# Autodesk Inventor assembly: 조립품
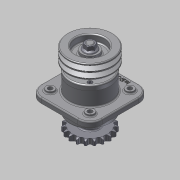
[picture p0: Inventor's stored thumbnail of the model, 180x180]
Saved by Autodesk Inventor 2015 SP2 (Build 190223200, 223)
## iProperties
Created: 2015-07
Part Number: 조립품
Document SubType Name: Assembly
Designer: AMC
Author: AMC
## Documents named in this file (12)
- C:\Users\AMC\Desktop\450735V1007\조립품.iam
- C:\Users\AMC\Desktop\450735V1007\본체.ipt
- C:\Users\AMC\Desktop\450735V1007\2-커버.ipt
- C:\Users\AMC\Desktop\450735V1007\3-축.ipt
- C:\Users\AMC\Desktop\450735V1007\4-V벨트풀리.ipt
- C:\Users\AMC\Desktop\450735V1007\5-체인 스프로킷.ipt
- C:\Users\AMC\Desktop\450735V1007\6-베어링 6206.ipt
- C:\Users\AMC\Desktop\450735V1007\7-부시.ipt
- C:\Users\AMC\Desktop\450735V1007\8-오일실 30x42.ipt
- C:\Users\AMC\Desktop\450735V1007\9-M16-너트.ipt
- C:\Users\AMC\Desktop\450735V1007\10-M6.ipt
- C:\Users\AMC\Desktop\450735V1007\11-키 6x6.ipt
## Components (22 placed, 10 different names)
1. 2-커버:1
2. 3-축:1
3. 4-V벨트풀리:1 — 각도:1
4. 5-체인 스프로킷:1 — 각도:2
5. 6-베어링 6206:1
6. 7-부시:1
7. 8-8-오일실 30x42:1
8. 9-M16 너트:1
9. 10-M6:1
10. 11-키 6x6:1 — 각도:2
11. 2-커버:2
12. 6-베어링 6206:2
13. 8-8-오일실 30x42:2
14. 10-M6:2
15. 10-M6:3
16. 10-M6:4
17. 10-M6:5
18. 10-M6:6
19. 10-M6:7
20. 10-M6:8
21. 11-키 6x6:2 — 각도:1
22. 9-M16 너트:2
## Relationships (2: Angle 2)
- 각도:1 [Angle]: 4-V벨트풀리:1 ↔ 11-키 6x6:2
- 각도:2 [Angle]: 5-체인 스프로킷:1 ↔ 11-키 6x6:1
